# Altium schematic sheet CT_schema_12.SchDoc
size 564 x 458 mm
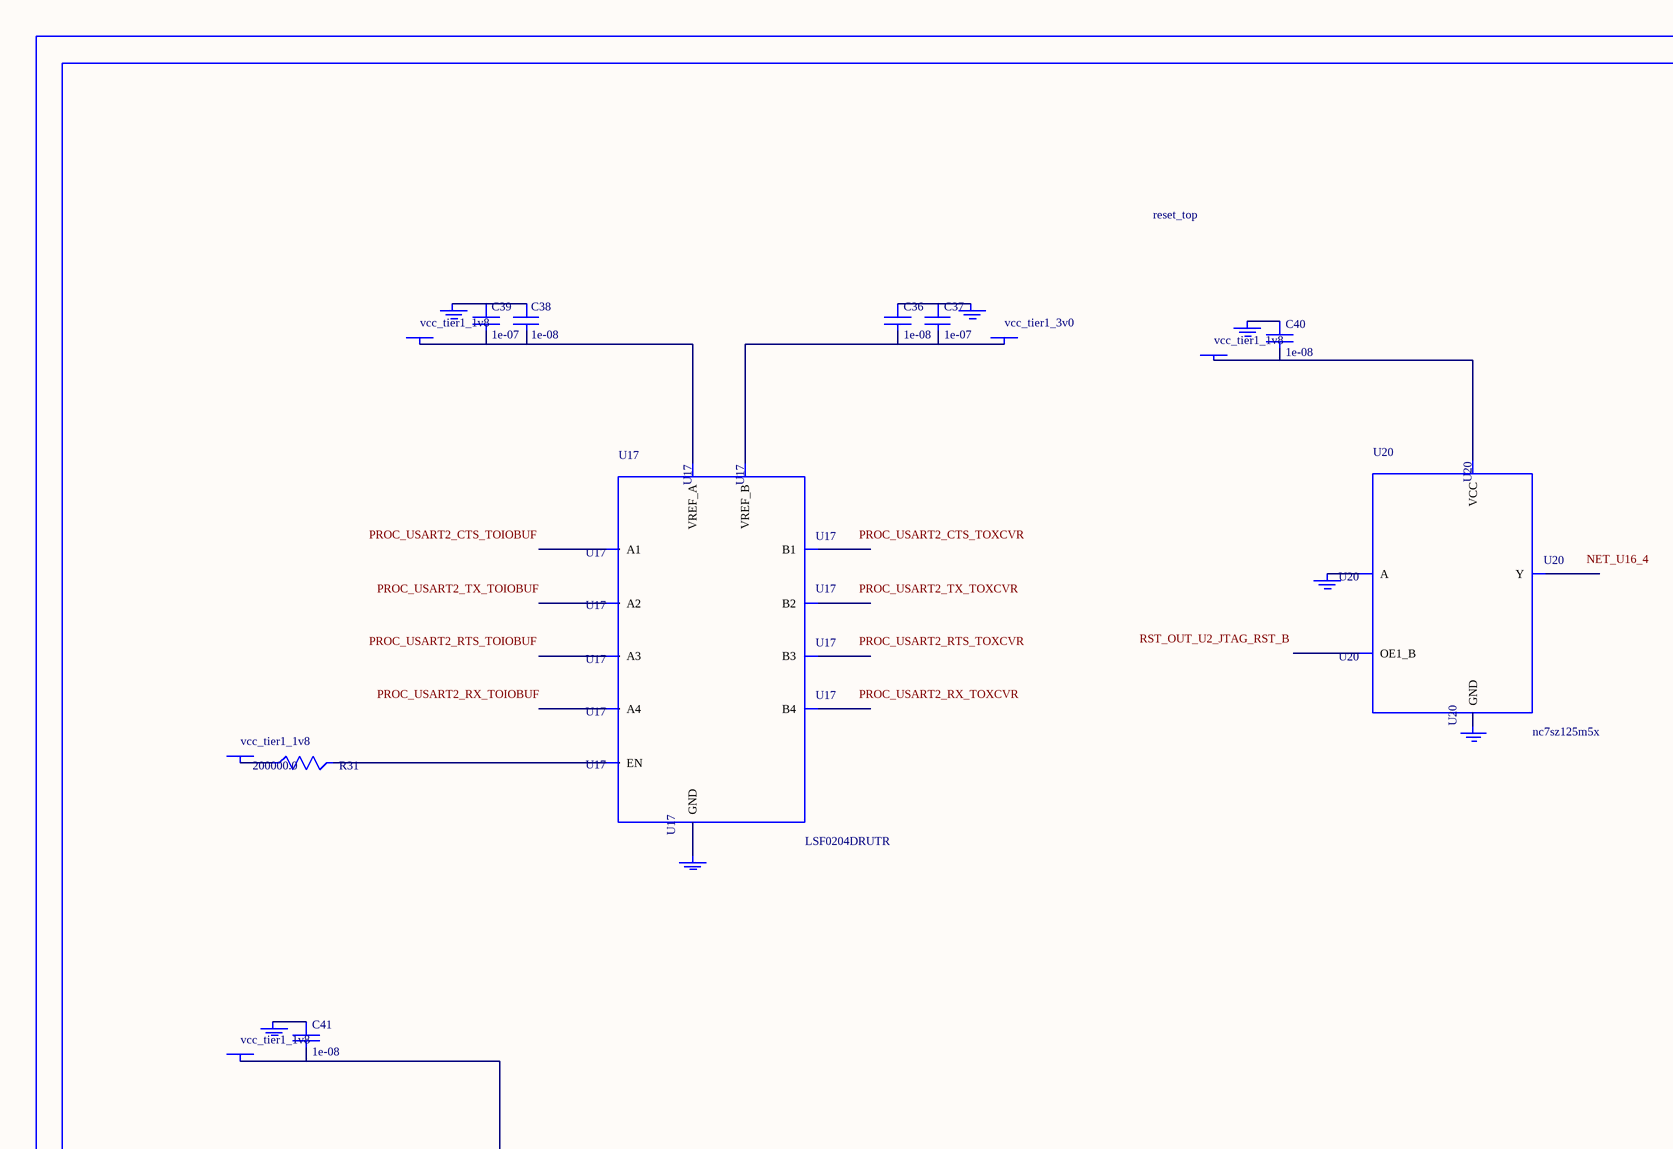
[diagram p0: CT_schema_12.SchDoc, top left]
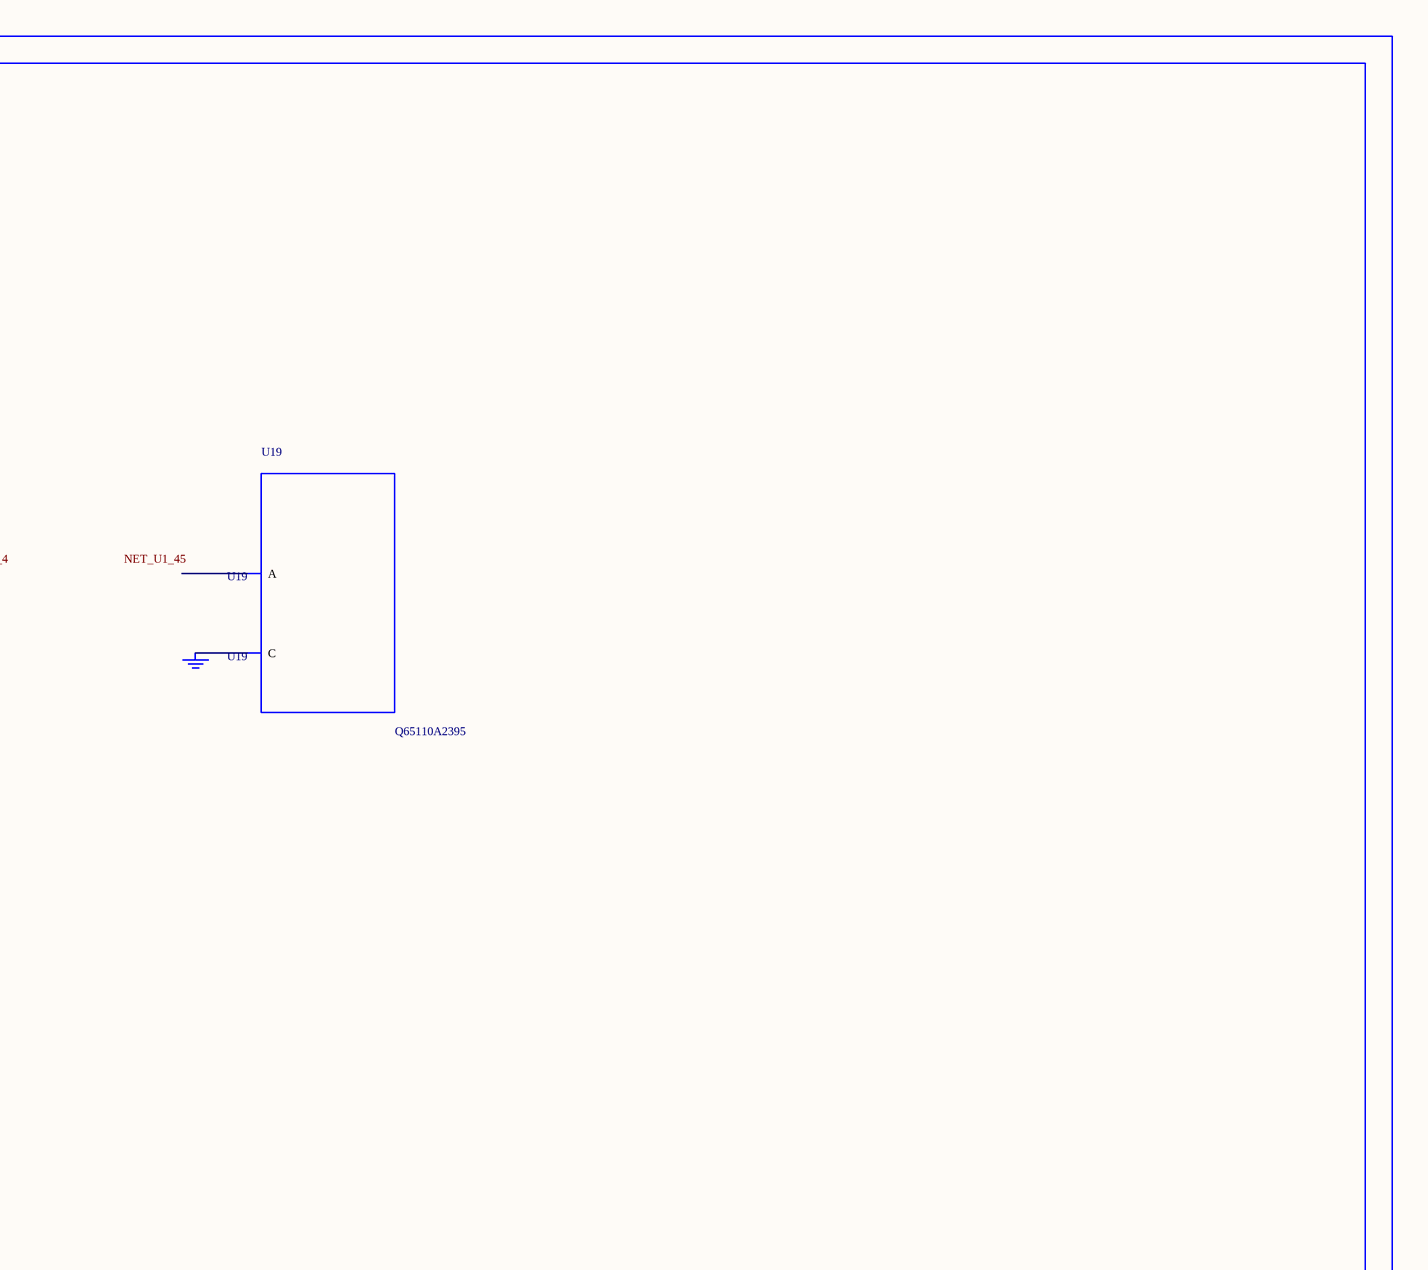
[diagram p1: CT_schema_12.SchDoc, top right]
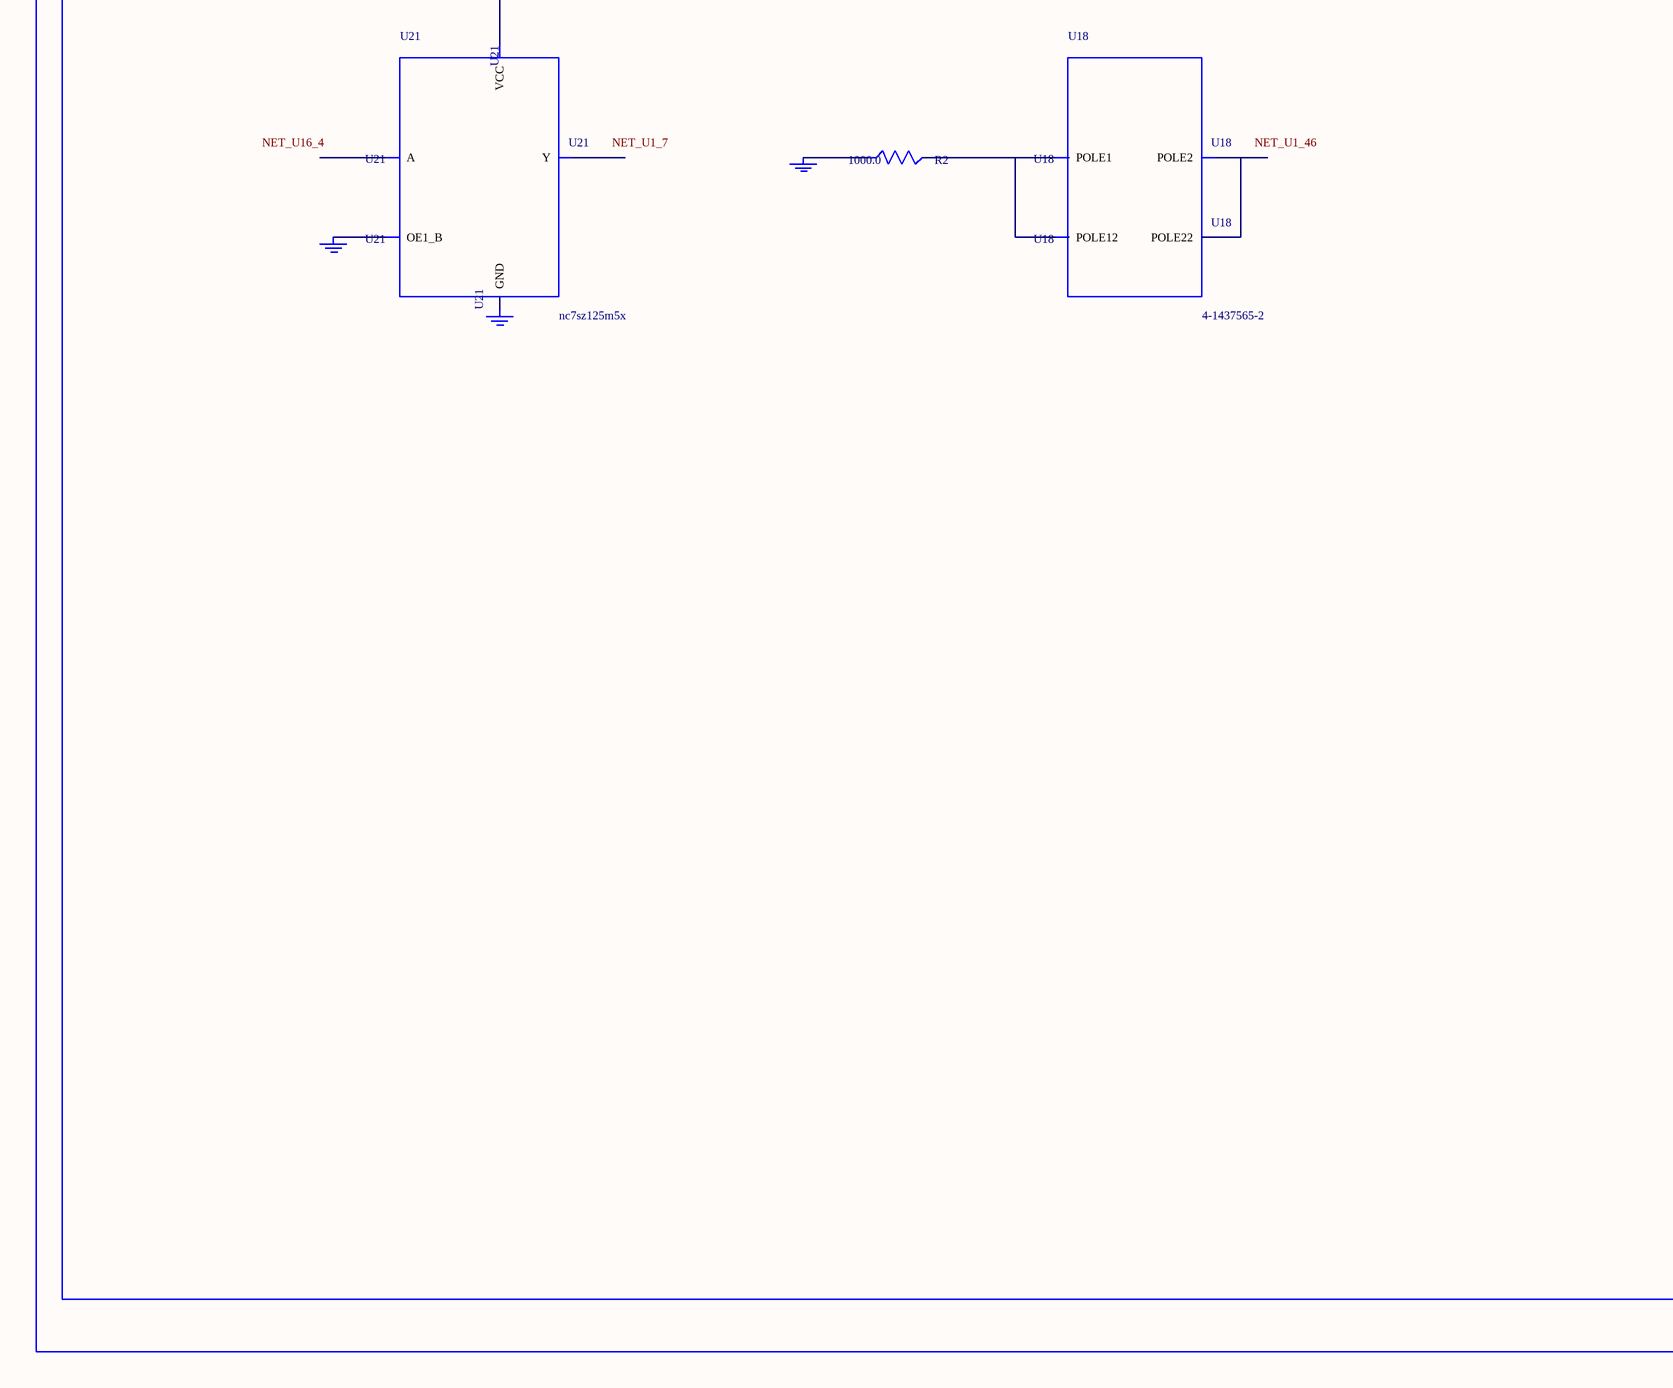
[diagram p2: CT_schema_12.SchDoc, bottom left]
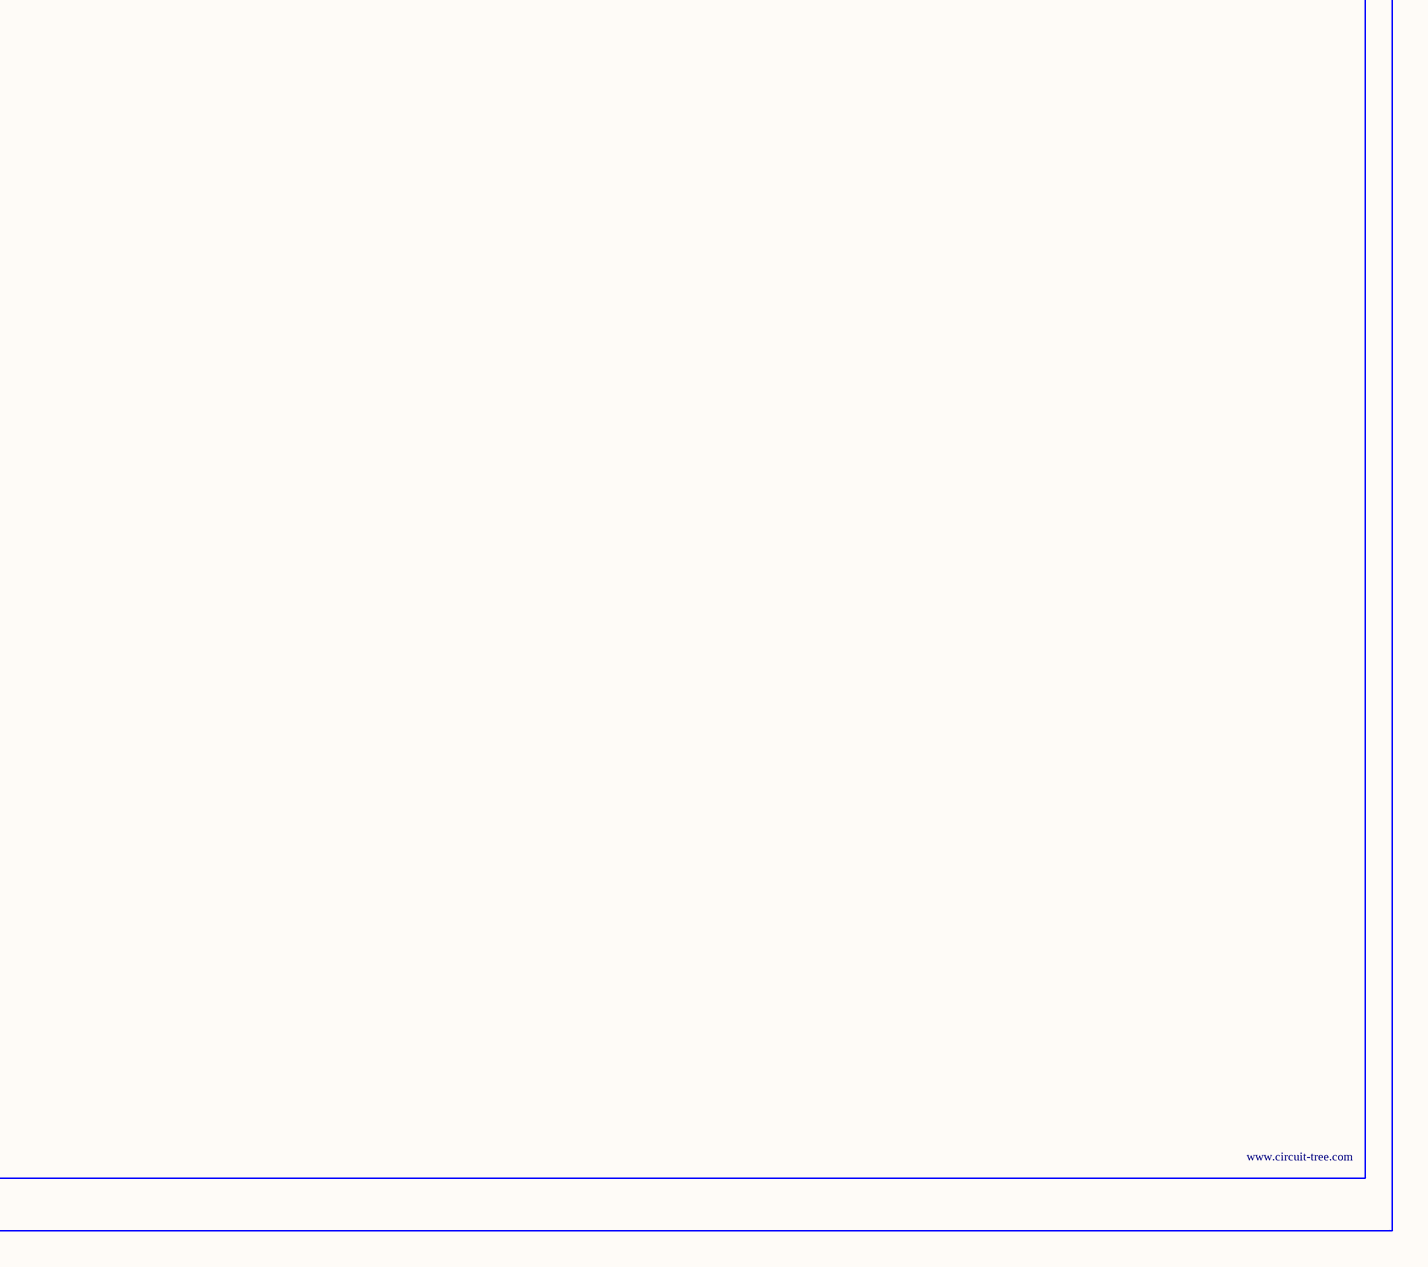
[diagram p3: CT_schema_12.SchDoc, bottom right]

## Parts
BORDER11  (no value)
C36  1e-08  [C0402]
C37  1e-07  [C0402]
C38  1e-08  [C0402]
C39  1e-07  [C0402]
C40  1e-08  [C0402]
C41  1e-08  [C0402]
GND_INSTANCE_11_0  (no value)
GND_INSTANCE_11_1  (no value)
GND_INSTANCE_11_2  (no value)
GND_INSTANCE_11_3  (no value)
GND_INSTANCE_11_4  (no value)
GND_INSTANCE_11_5  (no value)
GND_INSTANCE_11_6  (no value)
GND_INSTANCE_11_7  (no value)
GND_INSTANCE_11_8  (no value)
GND_INSTANCE_11_9  (no value)
GND_INSTANCE_11_10  (no value)
POWER_INSTANCE_11_0  vcc_tier1_1v8
POWER_INSTANCE_11_1  vcc_tier1_3v0
POWER_INSTANCE_11_2  vcc_tier1_1v8
POWER_INSTANCE_11_3  vcc_tier1_1v8
POWER_INSTANCE_11_4  vcc_tier1_1v8
R2  1000.0  [R0603]
R31  200000.0  [R0603]
U17  LSF0204DRUTR  [RUT0012A]
U18  4-1437565-2  [SW_4-1437565-2]
U19  Q65110A2395  [LGM67K-G1J2-24-Z]
U20  nc7sz125m5x  [NC7SZ125M5X]
U21  nc7sz125m5x  [NC7SZ125M5X]

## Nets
NetC36_1: C36.1 C37.1 GND_INSTANCE_11_1.0(GND)
NetC36_2: C36.2 C37.2 POWER_INSTANCE_11_1.0(PWR) U17.11(VREF_B)
NetC38_1: C38.1 C39.1 GND_INSTANCE_11_0.0(GND)
NetC38_2: C38.2 C39.2 POWER_INSTANCE_11_0.0(PWR) U17.1(VREF_A)
NetC40_1: C40.1 GND_INSTANCE_11_5.0(GND)
NetC40_2: C40.2 POWER_INSTANCE_11_3.0(PWR) U20.5(VCC)
NetC41_1: C41.1 GND_INSTANCE_11_8.0(GND)
NetC41_2: C41.2 POWER_INSTANCE_11_4.0(PWR) U21.5(VCC)
NetGND_INSTANCE_11_2_0: GND_INSTANCE_11_2.0(GND) U17.6(GND)
NetGND_INSTANCE_11_3_0: GND_INSTANCE_11_3.0(GND) R2.1
NetGND_INSTANCE_11_4_0: GND_INSTANCE_11_4.0(GND) U19.C
NetGND_INSTANCE_11_6_0: GND_INSTANCE_11_6.0(GND) U20.2(A)
NetGND_INSTANCE_11_7_0: GND_INSTANCE_11_7.0(GND) U20.3(GND)
NetGND_INSTANCE_11_9_0: GND_INSTANCE_11_9.0(GND) U21.1(OE1_B)
NetGND_INSTANCE_11_10_0: GND_INSTANCE_11_10.0(GND) U21.3(GND)
NetPOWER_INSTANCE_11_2_0: POWER_INSTANCE_11_2.0(PWR) R31.1
NetR2_2: R2.2 U18.1(POLE1) U18.2(POLE12)
NetR31_2: R31.2 U17.12(EN)
NetU18_3: U18.3(POLE2) U18.4(POLE22)

Not connected (* = marked no-connect by the designer): U17 2(A1) 3(A2) 4(A3) 5(A4) 7(B4) 8(B3) 9(B2) 10(B1); U19 A; U20 1(OE1_B) 4(Y); U21 2(A) 4(Y)

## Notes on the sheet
- Labels drawn without touching a wire or pin: NET_U1_7, NET_U1_45, NET_U1_46, NET_U16_4, PROC_USART2_CTS_TOIOBUF, PROC_USART2_CTS_TOXCVR, PROC_USART2_RTS_TOIOBUF, PROC_USART2_RTS_TOXCVR, PROC_USART2_RX_TOIOBUF, PROC_USART2_RX_TOXCVR, PROC_USART2_TX_TOIOBUF, PROC_USART2_TX_TOXCVR, RST_OUT_U2_JTAG_RST_B

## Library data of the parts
BORDER11 = BORDER_PAGE11
C36 C38 C40 C41 = C0402C103K3RAC
C37 C39 = C0402C104K3RACTU
GND_INSTANCE_11_0-GND_INSTANCE_11_10 = GND
POWER_INSTANCE_11_0-POWER_INSTANCE_11_4 = PWR
R2 = RC0603JR-071KL
R31 = RC0603JR-07200KL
